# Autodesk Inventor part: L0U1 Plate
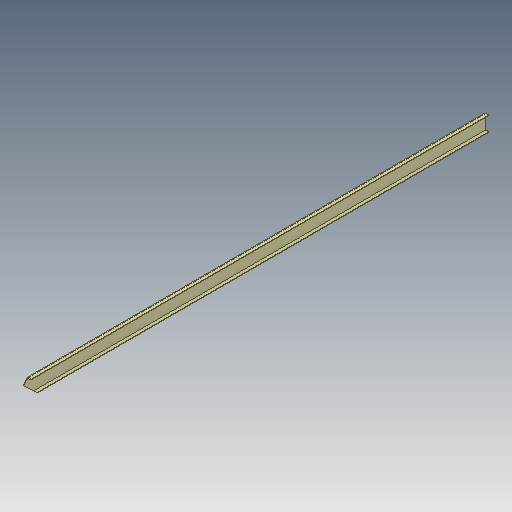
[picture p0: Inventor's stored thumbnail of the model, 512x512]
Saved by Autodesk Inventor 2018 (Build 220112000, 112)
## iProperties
Created: 2018-02
Part Number: L0U1 Plate
Material: Steel, Mild
Document SubType Name: Modeling
Designer: STK
Density: 7.85 g/cm^3
Appearance: Smooth - Ash
Author: STK
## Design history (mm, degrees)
sketch "Sketch1"
  geometry: L1 (12.7, 177.8)-(12.7, -177.8); L2 (0, -190.5)-(0, 190.5); L3 (0, -190.5)-(92.075, -190.5); L4 (92.075, -190.5)-(92.075, -177.8); L5 (92.075, -177.8)-(12.7, -177.8); L6 (0, 190.5)-(92.075, 190.5); L7 (92.075, 190.5)-(92.075, 177.8); L8 (92.075, 177.8)-(12.7, 177.8); L9 (0, 0)-(92.075, 0)
  constraints: 18 end point, 3 horizontal, 3 parallel, 2 equal length, 2 perpendicular, 2 vertical alignment, 1 point on line, 1 other
  dimensions: "d0" = 381 distance between parallel lines of L6 L3; "d1" = 92.075 distance of L2.end L6.end; "d2" = 12.7 distance between parallel lines of L2 L1; "d3" = 12.7 distance between parallel lines of L5 L3
extrude "Extrusion1" new body sketch "Sketch1" stored distance "d4" = 11887.2; taper "d5" = 0 deg
sketch "Sketch3"
  geometry: L1 (5208.737, -5473.469)-(-136.194, 252.93) reference; L2 (-136.194, 252.93)-(-407.176, 0); L3 (-11887.2, 0)-(0, 0) reference; L4 (-136.194, 252.93)-(-255.733, 381); L5 (-11887.2, 381)-(0, 381) reference; L6 (-255.733, 381)-(0, 381); L7 (0, 381)-(0, 0) reference; L8 (0, 0)-(-407.176, 0); 1 further point
  constraints: 8 end point, 2 collinear, 2 point on line
extrude "Extrusion3" cut sketch "Sketch3" extent not by distance; stored distance "d9" = 12700; taper "d10" = 0 deg
sketch "Sketch4"
  geometry: L1 (0, 0)-(408.192, 381); L2 (-270.982, -252.93)-(-7.543, -7.041) reference; L3 (0, 381)-(11631.467, 381) reference; L4 (0, 381)-(0, 0); L5 (0, 381)-(408.192, 381); 1 further point
  constraints: 6 end point, 1 collinear, 1 perpendicular, 1 point on line
extrude "Extrusion4" cut sketch "Sketch4" extent not by distance; stored distance "d11" = 12700; taper "d12" = 0 deg
body "Solid1"
node "Reference1"
node "Reference2"
